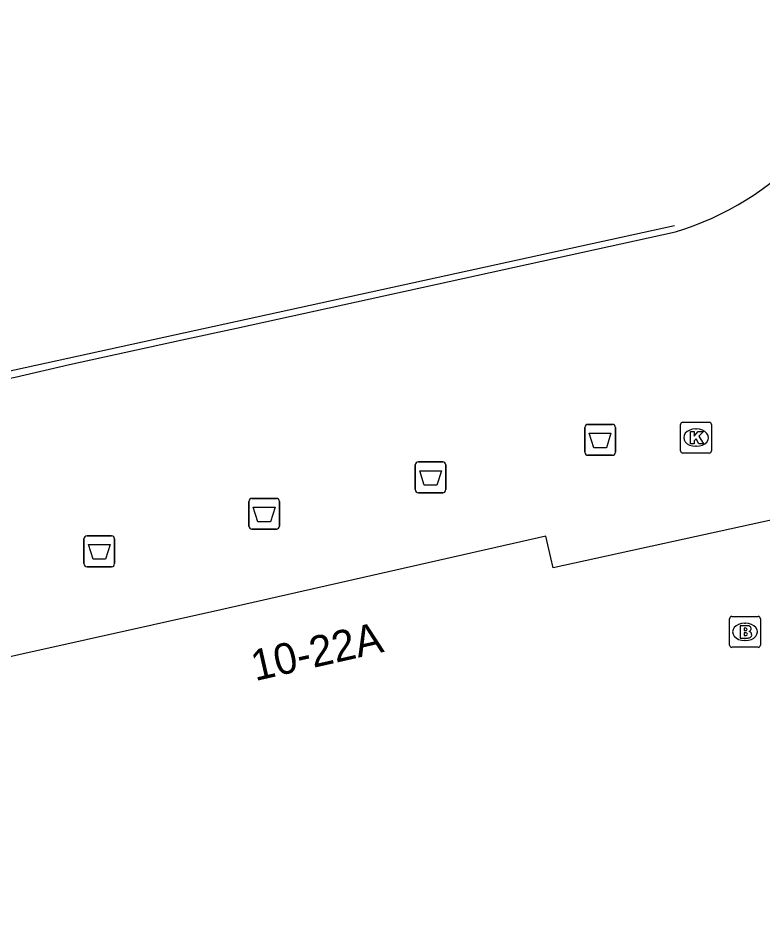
# Model space of a CAD drawing. Extents: x 160806 to 161707, y 383697 to 384148.
# Drawn here: x 161373.62 to 161397.72, y 383818.32 to 383847.75 of the extents above; entities that cross this region are included whole.
import ezdxf

# ---------------------------------------------------------------- set-up
doc = ezdxf.new("R2010")
doc.units = 0
for name, color, linetype in [('IMGEO_Afvalbak', 7, 'Continuous'), ('IMGEO_Brandkraan', 7, 'Continuous'), ('IMGEO_Kolk', 7, 'Continuous'), ('IMGEO_Lijnafwatering', 7, 'Continuous'), ('IMGEO_OVBaan_gesloten', 7, 'Continuous'), ('IMGEO_Pand', 7, 'Continuous'), ('IMGEO_Pand_nummerreeks', 7, 'Continuous')]:
    doc.layers.add(name, color=color, linetype=linetype)

msp = doc.modelspace()

# ---------------------------------------------------------------- linework, layer by layer
at = {"layer": 'IMGEO_Afvalbak'}
for p, q in [((161392.061, 383834.592), (161392.851, 383834.592)), ((161392.851, 383834.592), (161392.061, 383834.592)), ((161391.961, 383833.692), (161391.961, 383834.492)), ((161391.961, 383834.492), (161391.961, 383833.692)), ((161392.951, 383834.492), (161392.951, 383833.692)), ((161392.951, 383833.692), (161392.951, 383834.492)), ((161392.851, 383833.592), (161392.061, 383833.592)), ((161392.061, 383833.592), (161392.851, 383833.592)), ((161386.473, 383832.478), (161386.473, 383833.278)), ((161386.473, 383833.278), (161386.473, 383832.478)), ((161386.573, 383833.378), (161387.363, 383833.378)), ((161387.363, 383833.378), (161386.573, 383833.378)), ((161387.463, 383833.278), (161387.463, 383832.478)), ((161387.463, 383832.478), (161387.463, 383833.278)), ((161387.363, 383832.378), (161386.573, 383832.378)), ((161386.573, 383832.378), (161387.363, 383832.378)), ((161381.086, 383831.297), (161381.086, 383832.097)), ((161381.086, 383832.097), (161381.086, 383831.297)), ((161381.186, 383832.197), (161381.976, 383832.197)), ((161381.976, 383832.197), (161381.186, 383832.197)), ((161382.076, 383832.097), (161382.076, 383831.297)), ((161382.076, 383831.297), (161382.076, 383832.097)), ((161381.976, 383831.197), (161381.186, 383831.197)), ((161381.186, 383831.197), (161381.976, 383831.197)), ((161375.748, 383830.083), (161375.748, 383830.883)), ((161375.748, 383830.883), (161375.748, 383830.083)), ((161375.848, 383830.983), (161376.638, 383830.983)), ((161376.638, 383830.983), (161375.848, 383830.983)), ((161376.738, 383830.883), (161376.738, 383830.083)), ((161376.738, 383830.083), (161376.738, 383830.883)), ((161376.638, 383829.983), (161375.848, 383829.983)), ((161375.848, 383829.983), (161376.638, 383829.983))]:
    msp.add_line(p, q, dxfattribs=at)
for points in [[(161392.104, 383834.306), (161392.808, 383834.306), (161392.659, 383833.836), (161392.253, 383833.836), (161392.104, 383834.306)], [(161386.616, 383833.092), (161387.32, 383833.092), (161387.171, 383832.622), (161386.765, 383832.622), (161386.616, 383833.092)], [(161381.229, 383831.911), (161381.933, 383831.911), (161381.784, 383831.441), (161381.378, 383831.441), (161381.229, 383831.911)], [(161375.891, 383830.697), (161376.595, 383830.697), (161376.446, 383830.227), (161376.04, 383830.227), (161375.891, 383830.697)]]:
    msp.add_lwpolyline(points, dxfattribs=at)
for centre, start, end in [((161392.061, 383834.492), 90, 180), ((161392.061, 383834.492), 90, 180), ((161392.851, 383834.492), 0, 90), ((161392.851, 383834.492), 360, 90), ((161392.061, 383833.692), 180, 270), ((161392.061, 383833.692), 180, 270), ((161392.851, 383833.692), 270, 0), ((161392.851, 383833.692), 270, 0), ((161386.573, 383833.278), 90, 180), ((161386.573, 383833.278), 90, 180), ((161387.363, 383833.278), 0, 90), ((161387.363, 383833.278), 360, 90), ((161386.573, 383832.478), 180, 270), ((161386.573, 383832.478), 180, 270), ((161387.363, 383832.478), 270, 0), ((161387.363, 383832.478), 270, 0), ((161381.186, 383832.097), 90, 180), ((161381.186, 383832.097), 90, 180), ((161381.976, 383832.097), 0, 90), ((161381.976, 383832.097), 360, 90), ((161381.186, 383831.297), 180, 270), ((161381.186, 383831.297), 180, 270), ((161381.976, 383831.297), 270, 0), ((161381.976, 383831.297), 270, 0), ((161375.848, 383830.883), 90, 180), ((161375.848, 383830.883), 90, 180), ((161376.638, 383830.883), 0, 90), ((161376.638, 383830.883), 360, 90), ((161375.848, 383830.083), 180, 270), ((161375.848, 383830.083), 180, 270), ((161376.638, 383830.083), 270, 0), ((161376.638, 383830.083), 270, 0)]:
    msp.add_arc(centre, 0.1, start, end, dxfattribs=at)
at = {"layer": 'IMGEO_Brandkraan'}
for p, q in [((161396.647, 383827.446), (161396.647, 383828.298)), ((161396.722, 383828.372), (161397.574, 383828.372)), ((161397.135, 383828.152), (161397.16, 383828.152)), ((161397.648, 383828.298), (161397.648, 383827.446)), ((161397.158, 383827.592), (161397.133, 383827.592)), ((161397.574, 383827.372), (161396.722, 383827.372))]:
    msp.add_line(p, q, dxfattribs=at)
for points in [[(161396.647, 383827.446), (161396.647, 383828.298)], [(161396.722, 383828.372), (161397.574, 383828.372)], [(161397.648, 383828.298), (161397.648, 383827.446)], [(161396.995, 383828.072), (161396.995, 383827.672), (161397.208, 383827.672)], [(161397.226, 383828.072), (161396.995, 383828.072)], [(161397.174, 383827.991), (161397.12, 383827.991), (161397.12, 383827.915)], [(161397.12, 383827.915), (161397.173, 383827.915)], [(161397.182, 383827.839), (161397.12, 383827.839), (161397.12, 383827.758)], [(161397.12, 383827.758), (161397.182, 383827.758)], [(161397.574, 383827.372), (161396.722, 383827.372)]]:
    msp.add_lwpolyline(points, dxfattribs=at)
for centre, radius, start, end in [((161396.724, 383828.296), 0.0765, 91.552, 178.448), ((161396.724, 383828.296), 0.0765, 91.552, 178.448), ((161397.572, 383828.296), 0.0765, 1.552, 88.448), ((161397.572, 383828.296), 0.0765, 1.552, 88.448), ((161397.175, 383827.953), 0.0379, 267.8285, 90.9355), ((161397.183, 383827.798), 0.0404, 269.8759, 90.5077), ((161397.23, 383827.927), 0.145, 59.4692, 91.5367), ((161397.255, 383827.974), 0.0922, 285.5137, 58.1501), ((161397.26, 383827.782), 0.105, 301.3115, 78.989), ((161397.214, 383827.923), 0.251, 268.6676, 293.5347), ((161396.724, 383827.448), 0.0765, 181.552, 268.448), ((161396.724, 383827.448), 0.0765, 181.552, 268.448), ((161397.572, 383827.448), 0.0765, 271.552, 358.448), ((161397.572, 383827.448), 0.0765, 271.552, 358.448)]:
    msp.add_arc(centre, radius, start, end, dxfattribs=at)
for centre, major_axis, ratio, start_param, end_param in [((161397.134, 383827.872), (-0.387, 0.002), 0.722429, 4.712389, 7.853982), ((161397.159, 383827.872), (-0.39, 0.002), 0.717154, 1.570796, 4.712389)]:
    msp.add_ellipse(centre, major_axis=major_axis, ratio=ratio, start_param=start_param, end_param=end_param, dxfattribs=at)
at = {"layer": 'IMGEO_Kolk'}
for p, q in [((161395.137, 383834.663), (161395.989, 383834.663)), ((161395.062, 383833.737), (161395.062, 383834.589)), ((161395.55, 383834.443), (161395.575, 383834.443)), ((161396.063, 383834.589), (161396.063, 383833.737)), ((161395.573, 383833.883), (161395.548, 383833.883)), ((161395.989, 383833.663), (161395.137, 383833.663))]:
    msp.add_line(p, q, dxfattribs=at)
for points in [[(161395.137, 383834.663), (161395.989, 383834.663)], [(161395.062, 383833.737), (161395.062, 383834.589)], [(161395.383, 383834.363), (161395.506, 383834.363), (161395.506, 383834.212), (161395.636, 383834.363), (161395.8, 383834.363), (161395.654, 383834.212), (161395.807, 383833.963), (161395.655, 383833.963), (161395.57, 383834.127), (161395.506, 383834.06), (161395.506, 383833.963), (161395.383, 383833.963), (161395.383, 383834.363)], [(161396.063, 383834.589), (161396.063, 383833.737)], [(161395.989, 383833.663), (161395.137, 383833.663)]]:
    msp.add_lwpolyline(points, dxfattribs=at)
for centre, start, end in [((161395.139, 383834.587), 91.552, 178.448), ((161395.139, 383834.587), 91.552, 178.448), ((161395.987, 383834.587), 1.552, 88.448), ((161395.987, 383834.587), 1.552, 88.448), ((161395.139, 383833.739), 181.552, 268.448), ((161395.139, 383833.739), 181.552, 268.448), ((161395.987, 383833.739), 271.552, 358.448), ((161395.987, 383833.739), 271.552, 358.448)]:
    msp.add_arc(centre, 0.0765, start, end, dxfattribs=at)
for centre, major_axis, ratio, start_param, end_param in [((161395.549, 383834.163), (-0.387, 0.002), 0.722429, 4.712389, 7.853982), ((161395.574, 383834.163), (-0.39, 0.002), 0.717154, 1.570796, 4.712389)]:
    msp.add_ellipse(centre, major_axis=major_axis, ratio=ratio, start_param=start_param, end_param=end_param, dxfattribs=at)
at = {"layer": 'IMGEO_Lijnafwatering'}
for points in [[(161394.865, 383841.025), (161377.297, 383837.18)], [(161377.297, 383837.18), (161358.544, 383833.075)]]:
    msp.add_lwpolyline(points, dxfattribs=at)
at = {"layer": 'IMGEO_OVBaan_gesloten'}
msp.add_lwpolyline([(161317.419, 383834.272), (161320.903, 383833.041), (161325.598, 383831.395), (161335.734, 383827.866), (161337.61, 383828.281), (161341.551, 383829.169), (161343.322, 383829.562), (161346.737, 383830.315), (161348.495, 383830.684), (161352.057, 383831.466), (161353.825, 383831.84), (161357.457, 383832.655), (161359.221, 383833.037), (161362.756, 383833.811), (161364.52, 383834.206), (161368.15, 383835.002), (161369.909, 383835.381), (161373.519, 383836.126), (161375.28, 383836.529), (161378.924, 383837.328), (161380.683, 383837.71), (161394.899, 383840.828)], dxfattribs=at)
msp.add_arc((161392.082, 383850.105), 9.695, 286.8908, 345.9254, dxfattribs=at)
at = {"layer": 'IMGEO_Pand'}
msp.add_lwpolyline([(161405.826, 383833.211), (161390.937, 383829.942), (161390.863, 383830.269), (161390.704, 383830.974), (161380.182, 383828.591), (161369.268, 383826.155), (161369.411, 383825.503), (161369.496, 383825.119), (161370.039, 383822.657), (161342.321, 383816.504)], dxfattribs=at)

# ---------------------------------------------------------------- texts
at = {"layer": 'IMGEO_Pand_nummerreeks'}
msp.add_text('10-22A', height=1, rotation=12.7999, dxfattribs=at).set_placement((161381.287, 383826.276))

doc.saveas('drawing.dxf')
